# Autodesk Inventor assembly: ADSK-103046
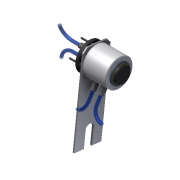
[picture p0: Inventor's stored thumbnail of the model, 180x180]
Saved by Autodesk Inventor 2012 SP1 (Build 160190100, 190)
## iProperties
Shininess: 20.0
Created: 2001-04
Part Number: ADSK-103046
Document SubType Name: Assembly
Designer: Administrator
Stock Number: ADSK-103046
Density: 0.0
Volumn: 0.0
Area: 0.0
PropertySet Name: Model Information
Control State: 0
Master: False
Checked Out: False
Author: Administrator
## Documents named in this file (11)
- D:\AOTC\Autodesk Inventor 2012 Essential for New Users\Autodesk Inventor 2012 Essentials - Project Files\Learning\Workspace\Sub-Assemblies\ADSK-103046.iam
- D:\AOTC\Autodesk Inventor 2012 Essential for New Users\Autodesk Inventor 2012 Essentials - Project Files\Learning\Workspace\Parts\0181E91D-77ED-C093-306F-EB07D3031A47.ipt
- D:\AOTC\Autodesk Inventor 2012 Essential for New Users\Autodesk Inventor 2012 Essentials - Project Files\Learning\Workspace\Parts\ADSK-103403.ipt
- D:\AOTC\Autodesk Inventor 2012 Essential for New Users\Autodesk Inventor 2012 Essentials - Project Files\Learning\Workspace\Parts\ADSK-103540.ipt
- D:\AOTC\Autodesk Inventor 2012 Essential for New Users\Autodesk Inventor 2012 Essentials - Project Files\Learning\Workspace\Parts\ADSK-104084.ipt
- D:\AOTC\Autodesk Inventor 2012 Essential for New Users\Autodesk Inventor 2012 Essentials - Project Files\Learning\Workspace\Parts\ADSK-103854.ipt
- D:\AOTC\Autodesk Inventor 2012 Essential for New Users\Autodesk Inventor 2012 Essentials - Project Files\Learning\Workspace\Parts\ADSK-103824.ipt
- D:\AOTC\Autodesk Inventor 2012 Essential for New Users\Autodesk Inventor 2012 Essentials - Project Files\Learning\Workspace\Parts\ADSK-103402.ipt
- D:\AOTC\Autodesk Inventor 2012 Essential for New Users\Autodesk Inventor 2012 Essentials - Project Files\Learning\Workspace\Parts\ADSK-103837.ipt
- D:\AOTC\Autodesk Inventor 2012 Essential for New Users\Autodesk Inventor 2012 Essentials - Project Files\Learning\Workspace\Parts\ADSK-103846.ipt
- D:\AOTC\Autodesk Inventor 2012 Essential for New Users\Autodesk Inventor 2012 Essentials - Project Files\Learning\Workspace\Parts\03C47DEB-7AD9-F39B-E702-CF9738ED4A72.ipt
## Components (27 placed, 10 different names)
1. ADSK-103540:1 — Insert:1, Insert:2, Insert:3, Insert:10, Insert:11, Insert:12, Insert:13, Insert:14, Insert:16, Insert:17, Insert:18, Insert:19, Insert:24, Insert:25
2. ADSK-103403:1 — Insert:4, Insert:5, Insert:15, Mate:1
3. ADSK-103854:1 — Insert:1
4. ADSK-103824:1 — Insert:3, Insert:9
5. ADSK-103824:2 — Insert:2, Insert:8
6. ADSK-103824:3 — Insert:4, Insert:7
7. ADSK-103824:4 — Insert:5, Insert:6
8. ADSK-103402:1 — Insert:7
9. ADSK-103402:2 — Insert:6
10. ADSK-103402:3 — Insert:8
11. ADSK-103402:4 — Insert:9
12. ADSK-103837:1 — Insert:10
13. ADSK-103837:2 — Insert:11
14. ADSK-103837:3 — Insert:12
15. ADSK-103837:4 — Insert:14
16. ADSK-103837:5 — Insert:13
17. ADSK-103846:1 — Insert:15, Mate:1, Insert:20, Insert:21, Insert:22, Insert:23, Insert:25
18. Hexagon Socket Countersunk Head Screw - M5 x  30:1 — Insert:20
19. Hexagon Socket Countersunk Head Screw - M5 x  30:2 — Insert:21
20. Hexagon Socket Countersunk Head Screw - M5 x  30:3 — Insert:23
21. Hexagon Socket Countersunk Head Screw - M5 x  30:4 — Insert:22
22. Hexagon Socket Head Cap Screw - No. 10 - 24 - 1 3/8:1 — Insert:19
23. Hexagon Socket Head Cap Screw - No. 10 - 24 - 1 3/8:2 — Insert:18
24. Hexagon Socket Head Cap Screw - No. 10 - 24 - 1 3/8:3 — Insert:16
25. Hexagon Socket Head Cap Screw - No. 10 - 24 - 1 3/8:4 — Insert:17
26. ADSK-104084:1
27. ADSK-104084:2 — Insert:24
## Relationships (26: Insert 25, Mate 1)
- Insert:1: ADSK-103540:1 ↔ ADSK-103854:1
- Insert:2: ADSK-103540:1 ↔ ADSK-103824:2
- Insert:3: ADSK-103540:1 ↔ ADSK-103824:1
- Insert:4: ADSK-103403:1 ↔ ADSK-103824:3
- Insert:5: ADSK-103403:1 ↔ ADSK-103824:4
- Insert:6: ADSK-103824:4 ↔ ADSK-103402:2
- Insert:7: ADSK-103824:3 ↔ ADSK-103402:1
- Insert:8: ADSK-103824:2 ↔ ADSK-103402:3
- Insert:9: ADSK-103824:1 ↔ ADSK-103402:4
- Insert:10: ADSK-103540:1 ↔ ADSK-103837:1
- Insert:11: ADSK-103540:1 ↔ ADSK-103837:2
- Insert:12: ADSK-103540:1 ↔ ADSK-103837:3
- Insert:13: ADSK-103540:1 ↔ ADSK-103837:5
- Insert:14: ADSK-103540:1 ↔ ADSK-103837:4
- Insert:15: ADSK-103403:1 ↔ ADSK-103846:1
- Mate:1: ADSK-103403:1 ↔ ADSK-103846:1
- Insert:16: ADSK-103540:1 ↔ Hexagon Socket Head Cap Screw - No. 10 - 24 - 1 3/8:3
- Insert:17: ADSK-103540:1 ↔ Hexagon Socket Head Cap Screw - No. 10 - 24 - 1 3/8:4
- Insert:18: ADSK-103540:1 ↔ Hexagon Socket Head Cap Screw - No. 10 - 24 - 1 3/8:2
- Insert:19: ADSK-103540:1 ↔ Hexagon Socket Head Cap Screw - No. 10 - 24 - 1 3/8:1
- Insert:20: ADSK-103846:1 ↔ Hexagon Socket Countersunk Head Screw - M5 x  30:1
- Insert:21: ADSK-103846:1 ↔ Hexagon Socket Countersunk Head Screw - M5 x  30:2
- Insert:22: ADSK-103846:1 ↔ Hexagon Socket Countersunk Head Screw - M5 x  30:4
- Insert:23: ADSK-103846:1 ↔ Hexagon Socket Countersunk Head Screw - M5 x  30:3
- Insert:24: ADSK-103540:1 ↔ ADSK-104084:2
- Insert:25: ADSK-103540:1 ↔ ADSK-103846:1
